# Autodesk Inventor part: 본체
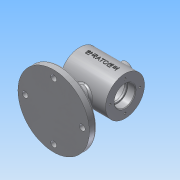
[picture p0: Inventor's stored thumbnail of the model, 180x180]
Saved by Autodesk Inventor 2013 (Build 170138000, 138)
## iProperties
Created: 2018-12
Part Number: 본체
Material: 알루미늄 6061
Document SubType Name: Modeling
Designer: Administrator
Mass: 687.627 g
Surface Area: 555.481 cm^2
Volume: 253.737 cm^3
Density: 2.71 g/cm^3
Author: Administrator
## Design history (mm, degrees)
sketch "스케치1"
  geometry: L1 (0, 30)-(35, 30); L2 (35, 30)-(35, 16); L3 (35, 16)-(23, 16); L4 (23, 16)-(23, 14); L5 (23, 14)-(20, 14); L6 (20, 14)-(20, 25); L7 (20, 25)-(0, 25); L8 (0, 25)-(0, 30); L9 (0, 0)-(35, 0)
  constraints: 18 end point, 6 parallel, 2 perpendicular, 2 point on line, 1 horizontal
  dimensions: "d0" = 60 diameter of L1 L9; "d2" = 50 diameter of L7 L9; "d4" = 28 diameter of L5 L9; "d5" = 32 diameter of L3 L9; "d6" = 20 distance between parallel lines of L6 L8; "d7" = 3 distance between parallel lines of L4 L6; "d8" = 35 distance of L1.start L1.end
revolve "회전1" sketch "스케치1" stored, may be unused: angle "d9" = 90 deg
sketch "스케치2"
  geometry: 2 further points
  constraints: 1 vertical alignment
  dimensions: "d10" = 23 distance of point (0, 0) point (0, 23)
hole "구멍1" sketch "스케치2" at (0, 23) diameter "d11" = 3.242; stored, may be unused: countersink angle "d15" = 90 deg, drill point angle "d17" = 118 deg; dims "d12" = 8, "d13" = 4, "d14" = 2, "d16" = 10
node "작업 평면1"
sketch "스케치3"
  geometry: C1 r 55 at (0, 0); 1 further point
  constraints: 1 centre point, 1 coincident
  dimensions: "d22" = 110 diameter of C1
extrude "돌출1" join sketch "스케치3" distance "d23" = 11; taper "d24" = 0 deg
sketch "스케치4"
  geometry: C1 r 55 at (0, 0); 1 further point
  constraints: 1 centre point, 1 coincident
  dimensions: "d25" = 110 diameter of C1
extrude "돌출2" join sketch "스케치4" distance "d26" = 50; taper "d27" = -75 deg
node "작업 평면2"
sketch "스케치6"
  geometry: C1 r 12 at (0, 0); 1 further point
  constraints: 1 centre point, 1 coincident
  dimensions: "d29" = 24 diameter of C1
extrude "돌출3" join sketch "스케치6" stored distance "d30" = 50; taper "d31" = 0 deg
node "작업 평면3"
sketch "스케치7"
  geometry: C1 r 10 at (0, 0); 1 further point
  constraints: 1 centre point, 1 coincident
  dimensions: "d33" = 20 diameter of C1
extrude "돌출4" join sketch "스케치7" stored distance "d34" = 50; taper "d35" = 0 deg
hole "구멍2" diameter "d38" = 10; stored, may be unused: countersink angle "d42" = 90 deg, drill point angle "d44" = 118 deg; dims "d36" = 10, "d37" = 10, "d39" = 8, "d40" = 4, "d41" = 2, "d43" = 10
node "작업 평면4"
sketch "스케치8"
  geometry: 2 further points
  constraints: 1 coincident, 1 other
feature "엠보싱1" sketch "스케치8" dims "d46" = 0.5, "d47" = 0
sketch "스케치9" dims "d48" = 88
  geometry: C1 r 4.5 at (0, -44); 2 further points
  constraints: 2 vertical alignment, 1 centre point, 1 coincident, 2 other
  dimensions: "d49" = 9 diameter of C1
extrude "돌출5" cut sketch "스케치9" distance "d50" = 10; taper "d51" = 0 deg
hole "구멍3" diameter "d54" = 14; stored, may be unused: countersink angle "d58" = 90 deg, drill point angle "d60" = 118 deg; dims "d52" = 10, "d53" = 10, "d55" = 8, "d56" = 4, "d57" = 2, "d59" = 10
fillet "모깎기1" dims "d64" = 3
fillet "모깎기2" dims "d65" = 0.3
chamfer "모따기1" distance "d66" = 1; stored, may be unused: second distance "d67" = 2, angle "d68" = 45 deg
node "솔리드1"
pattern_circular "원형 패턴1" dims angle "d19" = 360 deg
mirror "대칭1"
pattern_circular "원형 패턴2" dims angle "d62" = 360 deg
other parameters: "d21" = -75, "d28" = -75, "d32" = 37
